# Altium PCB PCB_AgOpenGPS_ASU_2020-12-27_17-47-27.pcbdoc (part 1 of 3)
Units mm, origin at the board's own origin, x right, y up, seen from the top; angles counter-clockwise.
Board outline 200.19 x 135.91 mm, 2 copper layers (Top Layer, Bottom Layer); 260 components, 183 nets, 970 pads, 382 vias.
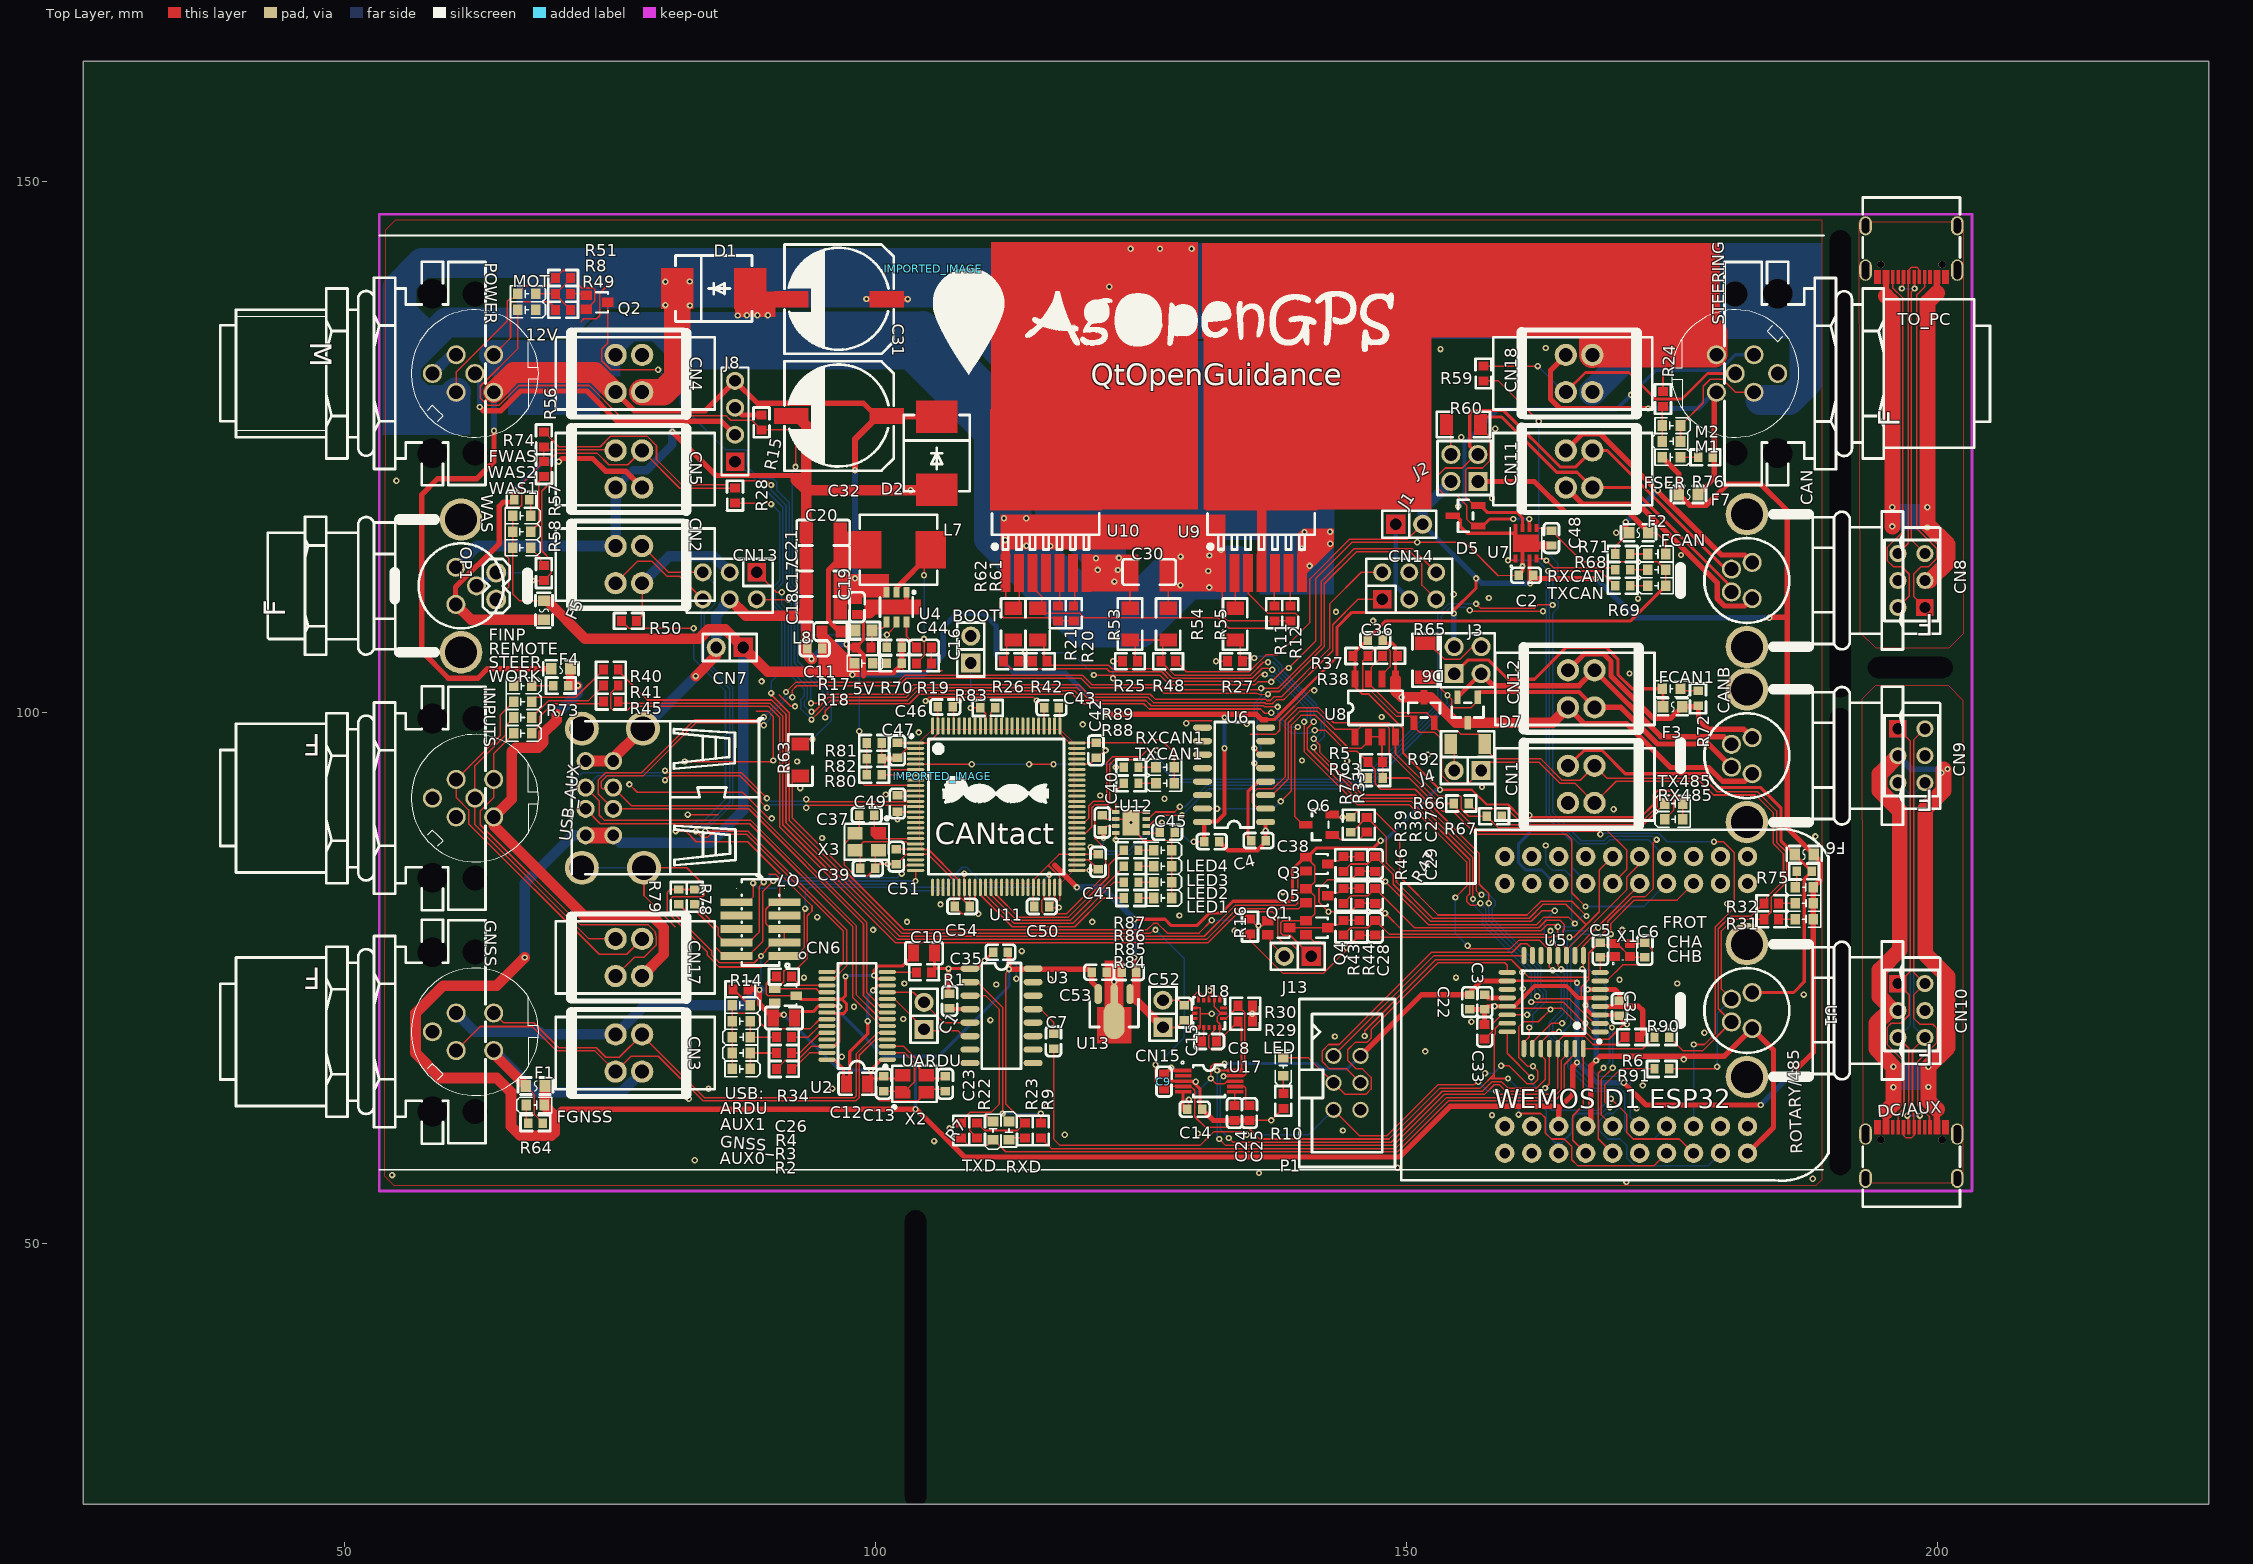
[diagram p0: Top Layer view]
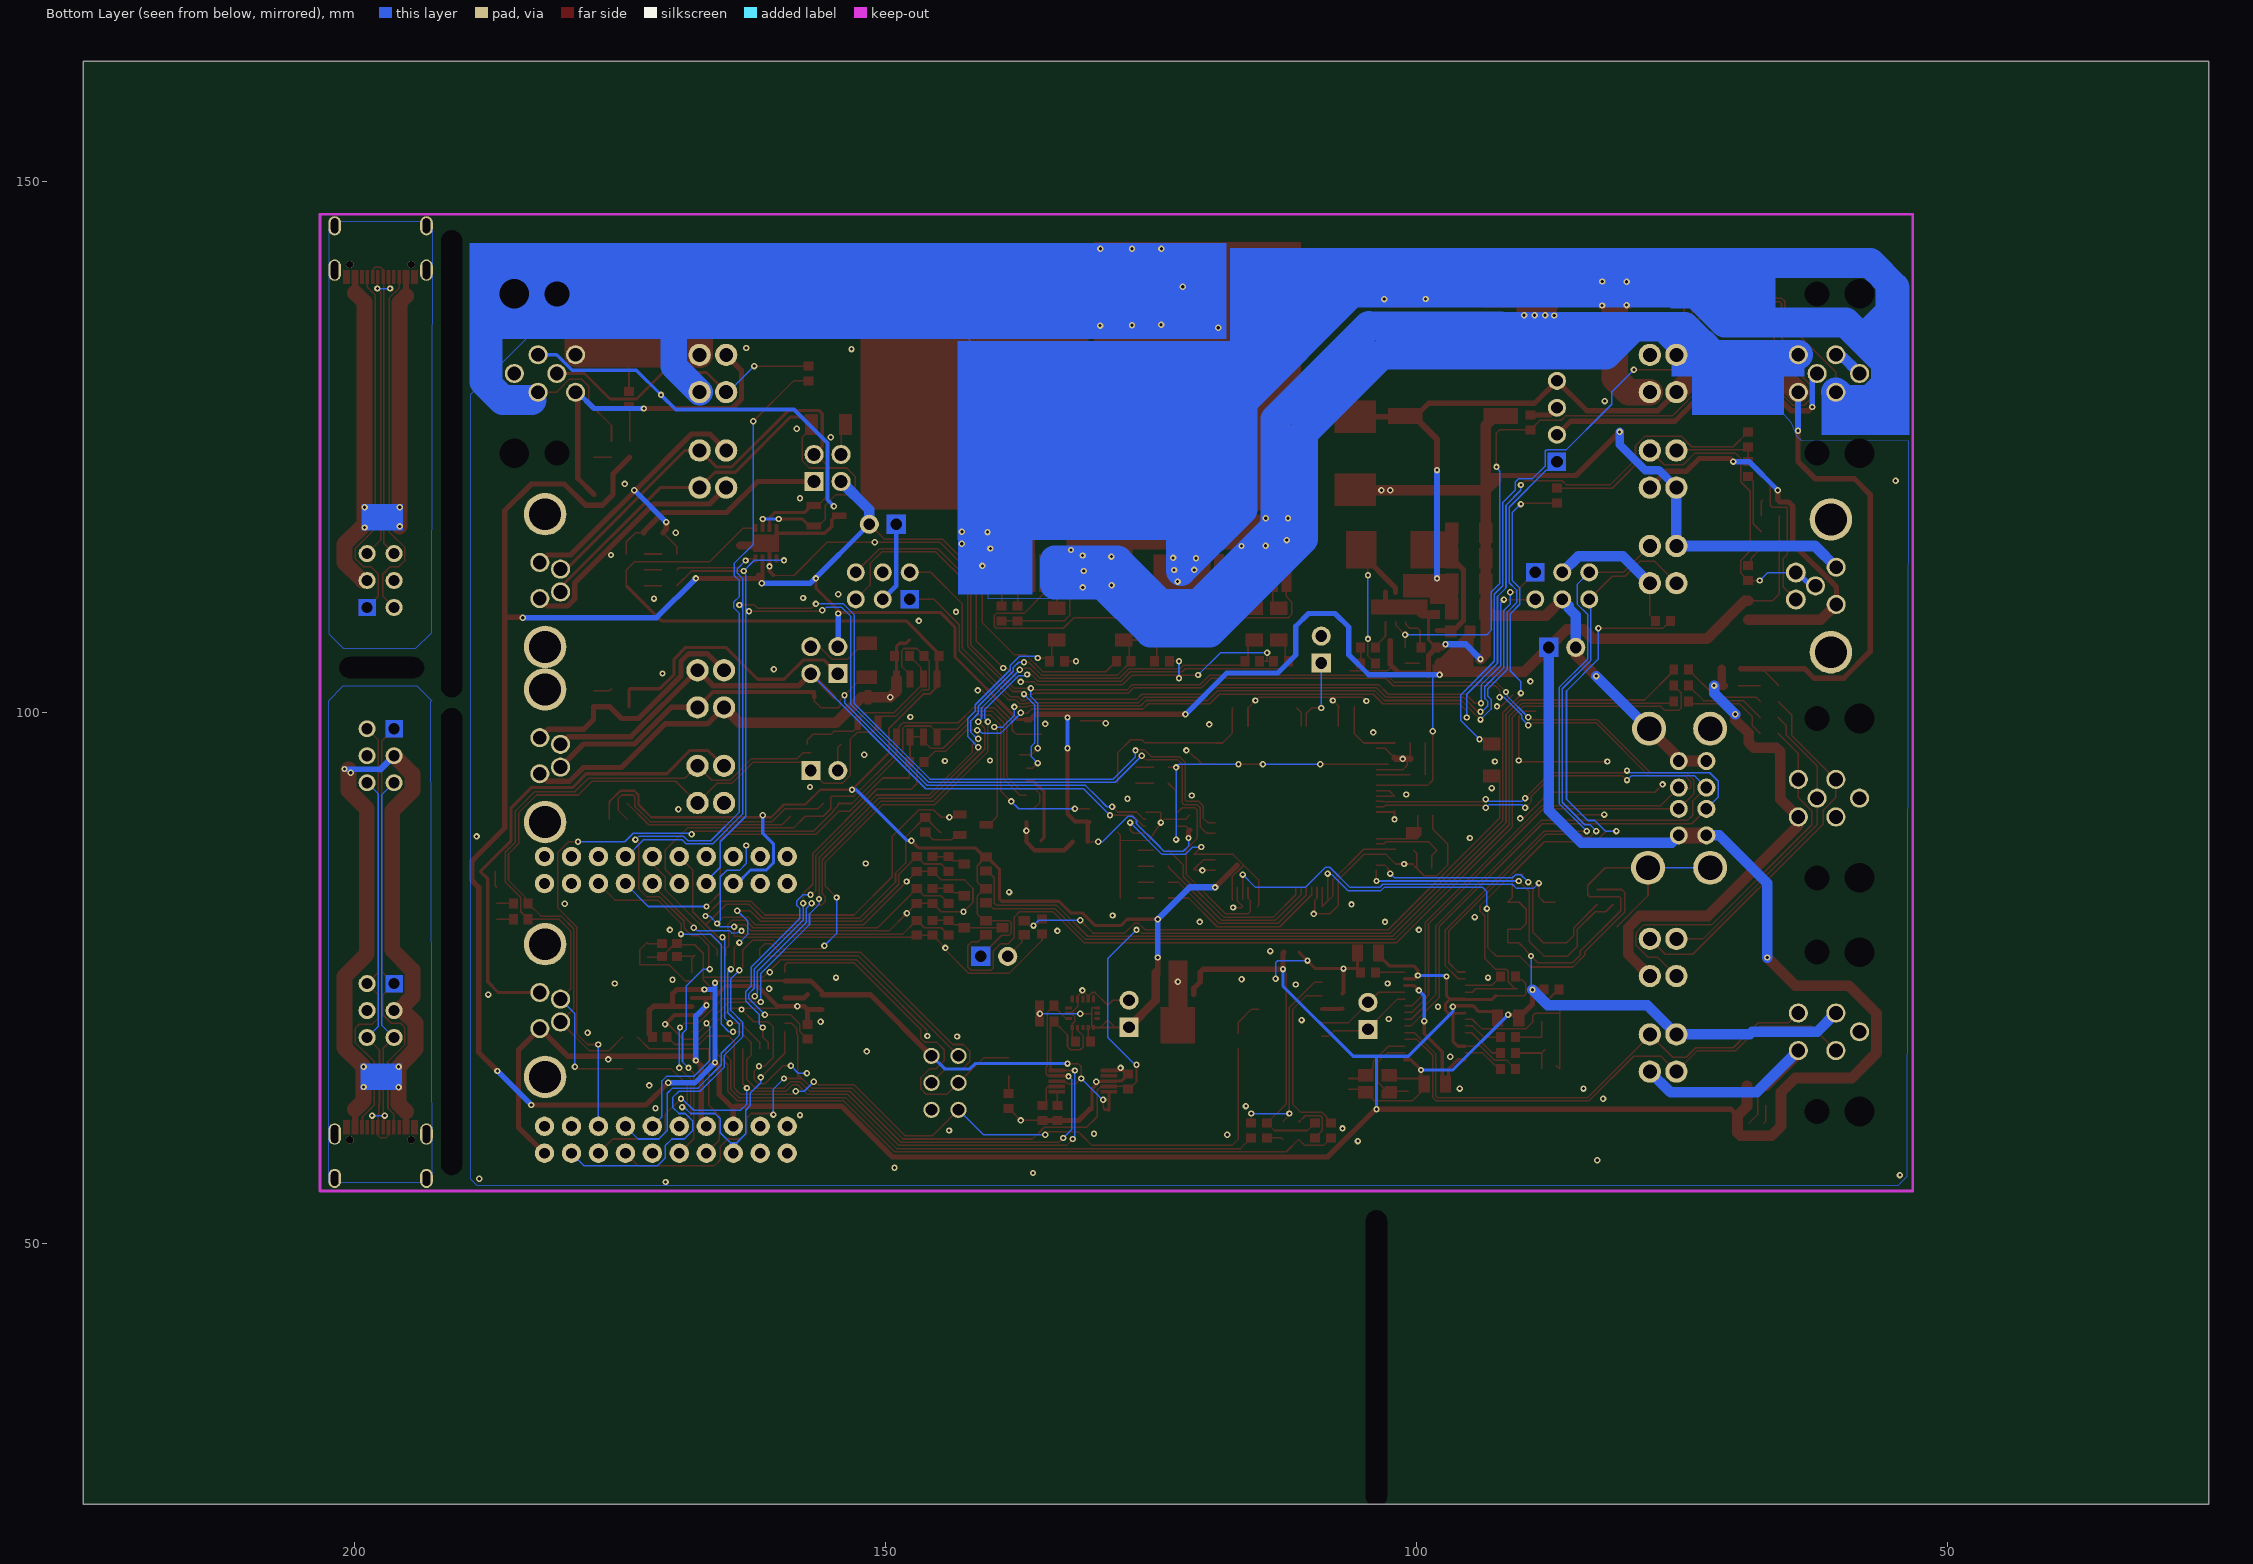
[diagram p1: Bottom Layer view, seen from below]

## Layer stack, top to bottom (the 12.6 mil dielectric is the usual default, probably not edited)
Top Layer: signal copper (thickness not stored)
Dielectric: dielectric 0.32, FR-4, Dk 4.8
Bottom Layer: signal copper (thickness not stored)

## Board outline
225.587,25.4 25.4,25.4 25.4,161.307 225.587,161.307

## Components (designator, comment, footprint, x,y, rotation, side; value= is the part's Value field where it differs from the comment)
5V "FC-D1608WD-460H5" LED0603-RD 98.887,104.6 r180 top
12V "FC-D1608WD-460H5" LED0603-RD 67.187,137.9 r180 top
ARDU "FC-D1608UGK-520D10" LED0603-RD 87.387,70.9 r180 top
AUX0 "FC-D1608UGK-520D10" LED0603-RD 87.387,66.4 r180 top
AUX1 "FC-DA1608BK-470H10" LED0603-RD 87.387,69.4 r0 top
BOOT "A2541WV-2P" HDR-TH_P2.54-H-M_A2541WV-2P#1 108.987,105.9 r90 top
C1 "1uF" C0603#1 106.987,72.8 r270 top
C2 "1uF" C0603#1 161.287,112.9 r180 top
C3 "100nF" C0603#1 157.387,72.7 r270 top
C4 "100nF" C0603#1 131.687,87.8 r0 top
C5 "22pF" C0603#1 168.287,77.6 r270 top
C6 "22pF" C0603#1 172.487,77.6 r90 top
C7 "100nF" C0603#1 116.787,69 r90 top
C8 "100nF" C0603#2 131.437,69 r180 top
C9 "1nF" C0603#2 127.187,65.2 r270 top
C10 "10uF" C0805 104.587,77.3 r180 top
C11 "1uF" C0603#1 94.287,106 r180 top
C12 "10uF" C0805 98.287,65 r180 top
C13 "33pF" C0603#1 100.787,65 r270 top
C14 "1uF" C0603#1 130.087,62.6 r0 top
C15 "1uF" C0603#1 129.087,71.7 r90 top
C16 "100nF" C0603#2 104.587,106.1 r0 top
C17 "10uF" C1206 95.087,112.1 r0 top
C18 "10uF" C1206 95.087,109.7 r0 top
C19 "100nF" C0603#2 98.287,109.9 r90 top
C20 "22uF" C1206 95.087,116.9 r0 top
C21 "22uF" C1206 95.087,114.5 r0 top
C22 "1uF" C0603#1 155.987,72.7 r270 top
C23 "33pF" C0603#1 106.587,65 r270 top
C24 "1nF" C0603#2 133.839,62.251 r90 top
C25 "1nF" C0603#2 135.239,62.251 r90 top
C26 "10uF" C0805 91.387,71.2 r180 top
C27 "100nF" C0603#2 147.087,85.7 r90 top
C28 "100nF" C0603#2 147.087,79.7 r90 top
C29 "100nF" C0603#2 147.087,82.7 r90 top
C30 "10uF" C1206 125.787,113.2 r180 top
C31 "470uF" CAP-SMD_BD10.0-L10.3-W10.3-FD 96.587,138.9 r180 top
C32 "470uF" CAP-SMD_BD10.0-L10.3-W10.3-FD 96.587,127.9 r180 top
C33 "1nF" C0603#2 157.387,69.9 r270 top
C34 "1uF" C0603#1 170.087,72.1 r270 top
C35 "1uF" C0603#1 111.787,77.4 r180 top
C36 "1uF" C0603#1 147.087,106.8 r0 top
C37 "33pF" C0603#1 99.187,90.3 r0 top
C38 "100nF" C0603#1 136.087,87.9 r0 top
C39 "33pF" C0603#1 99.287,85.3 r180 top
C40 "1uF" C0603#1 121.387,89.6 r90 top
C41 "1uF" C0603#1 120.987,85.9 r90 top
C42 "1uF" C0603#1 120.787,96.4 r90 top
C43 "1uF" C0603#1 116.587,100.4 r0 top
C44 "100nF" C0603#1 101.787,106.1 r180 top
C45 "100nF" C0603#1 127.487,88.7 r180 top
C46 "1uF" C0603#1 106.587,100.5 r180 top
C47 "1uF" C0603#1 102.087,96.4 r90 top
C48 "100nF" C0603#1 163.687,116.4 r90 top
C49 "1uF" C0603#3 102.087,91.4 r90 top
C50 "1uF" C0603#1 115.687,81.7 r180 top
C51 "1uF" C0603#1 101.987,86.4 r90 top
C52 "1uF" C0603#1 123.887,75.5 r180 top
C53 "1uF" C0603#1 121.087,75.5 r0 top
C54 "1uF" C0603#1 108.187,81.7 r0 top
CAN "M8 4pole female" "M8 FEMALE 4POLE 90°" 182.087,112.4 r90 top
CANB "M8 4pole female" "M8 FEMALE 4POLE 90°" 182.087,95.9 r90 top
CHA "FC-D1608HYK-588J" LED0603-RD 187.487,82 r0 top
CHB "FC-D1608HOK-600H" LED0603-RD 187.487,80.5 r0 top
CN1 "4x1 push_in connector" "S2C-SMT 3.50/04/180G 3.5SN BK RL" 166.487,93.2 r270 top
CN2 "4x1 push_in connector" "S2C-SMT 3.50/04/180G 3.5SN BK RL" 76.787,113.9 r90 top
CN3 "4x1 push_in connector" "S2C-SMT 3.50/04/180G 3.5SN BK RL" 76.787,67.9 r90 top
CN4 "4x1 push_in connector" "S2C-SMT 3.50/04/180G 3.5SN BK RL" 76.787,131.9 r90 top
CN5 "4x1 push_in connector" "S2C-SMT 3.50/04/180G 3.5SN BK RL" 76.787,122.9 r90 top
CN6 "1315-1206G0M075CP01" HDR-SMD_12P-P1.27-V-M-R2-C6-S7.50 89.187,80.2 r90 top
CN7 "A2541WV-2P" HDR-TH_P2.54-H-M_A2541WV-2P#2 86.287,106.1 r180 top
CN8 "A2541WV-2X3P" HDR-TH_6P-P2.54-V-R2-C3-S2.54_A2541WV-2X3P 197.587,112.4 r90 top
CN9 "A2541WV-2X3P" HDR-TH_6P-P2.54-V-R2-C3-S2.54_A2541WV-2X3P 197.587,95.9 r270 top
CN10 "A2541WV-2X3P" HDR-TH_6P-P2.54-V-R2-C3-S2.54_A2541WV-2X3P 197.587,71.9 r270 top
CN11 "4x1 push_in connector" "S2C-SMT 3.50/04/180G 3.5SN BK RL" 166.287,122.9 r270 top
CN12 "4x1 push_in connector" "S2C-SMT 3.50/04/180G 3.5SN BK RL" 166.487,102.2 r270 top
CN13 "PM254V-12-06-H85" HDR-TH_6P-P2.54-V-F-R2-C3-S2.54 86.287,111.9 r180 top
CN14 "PM254V-12-06-H85" HDR-TH_6P-P2.54-V-F-R2-C3-S2.54 150.287,111.9 r0 top
CN15 "A2541WV-2P" HDR-TH_P2.54-H-M_A2541WV-2P#1 127.087,71.6 r90 top
CN17 "4x1 push_in connector" "S2C-SMT 3.50/04/180G 3.5SN BK RL" 76.787,76.9 r90 top
CN18 "4x1 push_in connector" "S2C-SMT 3.50/04/180G 3.5SN BK RL" 166.287,131.9 r270 top
D1 "SMCJ28A-C140808" SMC_L6.9-W5.9-LS7.9-RD 84.787,139.9 r0 top
D2 "SMCJ28A-C140808" SMC_L6.9-W5.9-LS7.9-RD 105.787,124.4 r270 top
D5 "CDSOT23-T24CAN" SOT-23_L2.9-W1.3-P0.95-LS2.4-BR#1 155.587,118.5 r0 top
D6 "CDSOT23-T24CAN" SOT-23_L2.9-W1.3-P0.95-LS2.4-BR#1 151.687,100.2 r270 top
D7 "CDSOT23-T24CAN" SOT-23_L2.9-W1.3-P0.95-LS2.4-BR#2 155.787,100.2 r90 top
DC/AUX "KH-TYPE-C-16P" USB-C-SMD_KH-TYPE-C-16P#1 197.587,58.5 r0 top
F1 "BSMD0603-050-6V" F0603 67.987,64.8 r0 top
F2 "BSMD0603-050-6V" F0603 171.887,116.9 r180 top
F3 "BSMD0603-050-6V" F0603 175.087,100.5 r0 top
F4 "BSMD0603-050-6V" F0603 70.387,104.1 r0 top
F5 "BSMD0603-050-6V" F0603 68.787,109.6 r270 top
F6 "BSMD0603-050-6V" F0603 187.487,86.6 r180 top
F7 "BSMD0603-050-6V" F0603 176.587,120.5 r0 top
FCAN "FC-DA1608HRK-620D" LED0603-FD 173.587,114.9 r180 top
FCAN1 "FC-DA1608HRK-620D" LED0603-FD 174.988,102.201 r0 top
FGNSS "FC-DA1608HRK-620D" LED0603-FD 67.987,63 r180 top
FINP "FC-DA1608HRK-620D" LED0603-FD 66.787,102.5 r0 top
FROT "FC-DA1608HRK-620D" LED0603-FD 187.487,83.5 r180 top
FSER "FC-DA1608HRK-620D" LED0603-FD 174.987,124 r0 top
FWAS "FC-DA1608HRK-620D" LED0603-FD 66.687,118.5 r0 top
GNSS "M12 4pole female" "M12-D FEMALE 4POLE 90°" 62.287,69.9 r90 top
GNSS_ "FC-DA1608BK-470H10" LED0603-RD 87.387,67.9 r0 top
IMPORTED_IMAGE "IMPORTED_IMAGE" IMPORTED_IMAGE 106.327,93.952 r0 top
IMPORTED_IMAGE "IMPORTED_IMAGE" IMPORTED_IMAGE 105.442,141.785 r0 top
INPUTS "M12A 5pole female" "M12-A FEMALE 4-5POLE 90°" 62.287,91.9 r90 top
J1 "A2541WV-2P" HDR-TH_P2.54-H-M_A2541WV-2P#2 150.287,117.7 r0 top
J2 "A2541WV-2X2P" HDR-TH_4P-P2.54-V-R2-C2-S2.54_A2541WV-2X2P 155.487,123 r90 top
J3 "A2541WV-2X2P" HDR-TH_4P-P2.54-V-R2-C2-S2.54_A2541WV-2X2P 155.787,104.9 r0 top
J4 "A2541WV-2P" HDR-TH_P2.54-H-M_A2541WV-2P#1 155.787,94.5 r180 top
J8 "A2541WV-4P" HDR-TH_4P-P2.54-V 86.787,127.4 r90 top
J13 "A2541WV-2P" HDR-TH_P2.54-H-M_A2541WV-2P#2 139.787,77 r180 top
L7 "5.6uH" IND-SMD_L7.3-W6.6_MHCI06030 102.187,115.3 r180 top
L8 "1500Ω" L0603 95.887,107.6 r180 top
LED "FC-DA1608HRK-620D" LED0603-FD 138.43,66.593 r270 top
LED1 "FC-D1608UGK-520D10" LED0603-RD 127.087,82.5 r180 top
LED2 "FC-DA1608BK-470H10" LED0603-RD 127.087,84 r180 top
LED3 "FC-D1608UGK-520D10" LED0603-RD 127.087,85.5 r180 top
LED4 "FC-DA1608BK-470H10" LED0603-RD 127.087,87 r180 top
M1 "FC-D1608HYK-588J" LED0603-RD 174.987,125.5 r0 top
M2 "FC-D1608HOK-600H" LED0603-RD 174.987,127 r180 top
MOT "FC-D1608WD-460H5" LED0603-RD 67.187,139.4 r180 top
OP1 "Option M8 4pole" 1X02 64.287,113.15 r270 top
P1 "HDR-IDC-2.54-2X3P" IDC-TH_6P-P2.54_C11214 144.429,65.092 r270 top
POWER "M12A 5pole male" "M12-A MALE 4-5POLE 90°" 62.287,131.9 r90 top
Q1 "BC856BW,115" SOT-323-3_L2.2-W1.3-P1.30-LS2.2-BR#1 137.987,79.7 r180 top
Q2 "BC856BW,115" SOT-323-3_L2.2-W1.3-P1.30-LS2.2-BR#1 73.787,138.6 r180 top
Q3 "BC856BW,115" SOT-323-3_L2.2-W1.3-P1.30-LS2.2-BR#1 141.587,85.7 r180 top
Q4 "BC856BW,115" SOT-323-3_L2.2-W1.3-P1.30-LS2.2-BR#1 141.587,79.7 r180 top
Q5 "BC856BW,115" SOT-323-3_L2.2-W1.3-P1.30-LS2.2-BR#1 141.587,82.7 r180 top
Q6 "ZXMS6004FFTA" SOT-23-3_L2.9-W1.6-P1.90-LS2.8-BR 141.787,89.4 r0 top
Q7 "BC856BW,115" SOT-323-3_L2.2-W1.3-P1.30-LS2.2-BR#2 91.537,73.3 r180 top
R1 "2.7k" R0603#1 104.587,75.5 r180 top
R2 "10K" R0603#1 91.387,66.4 r180 top
R3 "1K" R0603#1 91.387,67.9 r180 top
R4 "1K" R0603#1 91.387,69.4 r0 top
R5 "1K" R0603#1 147.087,95.3 r180 top
R6 "1K" R0603#1 171.287,69.4 r0 top
R7 "1K" R0603#1 108.087,60.6 r270 top
R8 "10K" R0603#1 70.587,139.4 r0 top
R9 "1K" R0603#1 115.587,60.6 r90 top
R10 "1K" R0603#1 138.429,63.392 r90 top
R11 "1K" R0603#1 137.587,109.3 r90 top
R12 "1K" R0603#1 139.087,109.3 r90 top
R14 "1K" R0603#1 87.287,73.9 r180 top
R15 "10K" R0603#1 89.287,127.3 r90 top
R16 "10K" R0603#1 135.287,79.8 r270 top
R17 "51K" R0603#2 98.887,107.7 r180 top
R18 "10K" R0603#1 98.887,106.1 r0 top
R19 "10" R0603#1 104.587,104.6 r0 top
R20 "1K" R0603#1 118.687,109.3 r270 top
R21 "1K" R0603#1 117.187,109.3 r270 top
R22 "1K" R0603#1 109.587,60.6 r90 top
R23 "1K" R0603#1 114.087,60.6 r90 top
R24 "2.7k" R0603#1 174.187,129.5 r90 top
R25 "2k2" R0603#1 123.987,104.8 r180 top
R26 "2k2" R0603#1 112.787,104.8 r0 top
R27 "2k2" R0603#1 133.887,104.8 r180 top
R28 "10K" R0603#1 86.787,120.4 r270 top
R29 "1K" R0603#1 134.839,70.851 r0 top
R30 "1K" R0603#1 134.839,72.351 r0 top
R31 "1K" R0603#1 184.387,80.5 r0 top
R32 "1K" R0603#1 184.387,82 r0 top
R33 "10K" R0603#1 146.287,89.4 r90 top
R34 "10K" R0603#1 91.387,75.1 r180 top
R36 "680R" R0603#1 145.587,85.7 r90 top
R37 "1K" R0603#1 145.687,105.3 r180 top
R38 "1K" R0603#1 148.487,105.3 r0 top
R39 "10K" R0603#1 144.087,85.7 r90 top
R40 "1K" R0603#1 75.087,104 r180 top
R41 "1K" R0603#1 75.087,102.5 r180 top
R42 "2k2" R0603#1 115.487,104.8 r180 top
R43 "10K" R0603#1 144.087,79.7 r90 top
R44 "680R" R0603#1 145.587,79.7 r90 top
R45 "1K" R0603#1 75.087,101 r180 top
R46 "10K" R0603#1 144.087,82.7 r90 top
R47 "680R" R0603#1 145.587,82.7 r90 top
R48 "10K" R0603#1 127.587,104.8 r180 top
R49 "10K" R0603#1 70.587,137.9 r0 top
R50 "10K" R0603#1 76.787,108.6 r180 top
R51 "10K" R0603#1 70.587,140.9 r180 top
R53 "8.2K" RES-SMD_L3.5-W1.5 123.987,108.3 r90 top
R54 "8.2K" RES-SMD_L3.5-W1.5 127.587,108.3 r90 top
R55 "8.2K" RES-SMD_L3.5-W1.5 133.887,108.3 r90 top
R56 "10K" R0603#1 68.787,125.7 r90 top
R57 "1K" R0603#1 68.787,122.9 r270 top
R58 "1K" R0603#1 68.787,113.1 r90 top
R59 "1K" R0603#1 157.287,131.9 r90 top
R60 "120" R1206#1 155.387,127.1 r180 top
R61 "8.2K" RES-SMD_L3.5-W1.5 115.287,108.3 r90 top
R62 "8.2K" RES-SMD_L3.5-W1.5 112.987,108.3 r270 top
R63 "8.2K" RES-SMD_L3.5-W1.5 92.937,95.5 r270 top
R64 "1K" R0603#3 67.987,61.3 r0 top
R65 "120" R1206#1 151.787,104.9 r90 top
R66 "1K" R0603#3 155.187,91.4 r180 top
R67 "1K" R0603#3 158.287,90.2 r180 top
R68 "1K" R0603#3 170.387,113.4 r180 top
R69 "1K" R0603#3 170.387,111.9 r180 top
R70 "10K" R0603#3 101.787,104.6 r180 top
R71 "2.7k" R0603#3 170.387,114.9 r180 top
R72 "2.7k" R0603#3 177.487,101.3 r270 top
R73 "10K" R0603#3 70.387,102.5 r0 top
R74 "10K" R0603#3 66.687,120 r180 top
R75 "1K" R0603#3 187.487,85 r0 top
R76 "1K" R0603#3 178.187,124 r180 top
R77 "10K" R0603#3 144.787,89.4 r90 top
R78 "10K" R0603#3 82.987,82.6 r270 top
R79 "10K" R0603#3 81.487,82.6 r270 top
R80 "10K" R0603#3 99.887,94.1 r180 top
R81 "2.7k" R0603#3 99.887,97.1 r0 top
R82 "10K" R0603#3 99.887,95.6 r0 top
R83 "10" R0603#3 110.587,100.4 r0 top
R84 "1K" R0603#3 124.087,82.5 r180 top
R85 "1K" R0603#3 124.087,84 r180 top
R86 "1K" R0603#3 124.087,85.5 r180 top
R87 "1K" R0603#3 124.087,87 r180 top
R88 "1K" R0603#3 124.087,93.3 r180 top
R89 "1K" R0603#3 124.087,94.8 r180 top
R90 "1K" R0603#3 174.087,69.4 r180 top
R91 "1K" R0603#3 174.087,66.4 r180 top
R92 "120" R1206#2 155.787,97 r0 top
R93 "10K" R0603#3 147.087,93.8 r180 top
REMOTE "FC-D1608HYK-588J" LED0603-RD 66.787,101 r180 top
ROTARY/485 "M8 4pole female" "M8 FEMALE 4POLE 90°" 182.087,71.9 r90 top
RX485 "FC-D1608UGK-520D10" LED0603-RD 175.187,89.9 r0 top
RXCAN "FC-D1608UGK-520D10" LED0603-RD 173.587,113.4 r0 top
RXCAN1 "FC-D1608UGK-520D10" LED0603-RD 127.287,94.8 r0 top
RXD "FC-D1608UGK-520D10" LED0603-RD 112.587,60.6 r270 top
STEER "FC-D1608HYK-588J" LED0603-RD 66.787,99.5 r180 top
STEERING "M12A 5pole female" "M12-A FEMALE 4-5POLE 90°" 180.987,131.9 r270 top
TO_PC "KH-TYPE-C-16P" USB-C-SMD_KH-TYPE-C-16P#2 197.587,143.4 r180 top
TX485 "FC-DA1608BK-470H10" LED0603-RD 175.187,91.4 r0 top
TXCAN "FC-DA1608BK-470H10" LED0603-RD 173.587,111.9 r0 top
TXCAN1 "FC-DA1608BK-470H10" LED0603-RD 127.287,93.3 r0 top
TXD "FC-DA1608BK-470H10" LED0603-RD 111.087,60.6 r90 top
U1 "TG_WEMOS_D1_ESP32(CLONE)" "WEMOS-D1 ESP32" 184.687,86.4 r270 top
U2 "FE1.1S" SSOP-28_L9.9-W3.9-P0.64-LS6.0-BL 98.287,71.4 r90 top
U3 "CH340B" SOIC-16_L9.9-W3.9-P1.27-LS6.0-BL 111.887,71.4 r270 top
U4 "TPS56339" SOT-23-6_L2.9-W1.6-P0.95-LS2.8-BL 101.987,109.9 r180 top
U5 "ATMEGA328P-AU" TQFP-32_L7.0-W7.0-P0.80-LS9.0-BL 163.887,72.7 r90 top
U6 "CH340B" SOIC-16_L9.9-W3.9-P1.27-LS6.0-BL 133.787,94.1 r90 top
U7 "TJA1051TK/3,118" HVSON-8_L3.0-W3.0-P0.65-BL-EP#1 161.287,115.9 r0 top
U8 "KY3485LEEN" SO-8_L4.9-W3.9-P1.27-LS5.9-BL 147.087,100.4 r0 top
U9 "BTN8982TAAUMA1" TO-263-7_L10.2-W10.4-P1.27-LS14.4-B 136.387,118.45 r270 top
U10 "BTN8982TAAUMA1" TO-263-7_L10.2-W10.4-P1.27-LS14.4-B 116.087,118.45 r270 top
U11 "LPC54616J512BD100" TQFP-100_14X14X05P 105.387,98.7 r0 top
U12 "TJA1051TK/3,118" HVSON-8_L3.0-W3.0-P0.65-BL-EP#2 124.087,89.6 r270 top
U13 "UR133AG-33-AB3-B-R" SOT-89_L4.5-W2.5-P1.50-LS4.2-BR 122.487,72.2 r90 top
U17 "ADS1115IDGSR" MSOP-10_L3.0-W3.0-P0.50-LS5.0-BL 131.439,65.251 r270 top
U18 "MMA8452QR1_C11360" QFN-16_L3.0-W3.0-P0.50-TL_MMA8452QR1 131.439,71.651 r90 top
UARDU "A2541WV-2P" HDR-TH_P2.54-H-M_A2541WV-2P#1 104.588,71.401 r90 top
USB: "FC-D1608UGK-520D10" LED0603-RD 87.387,72.4 r180 top
USB_AUX "Double layer DIP 90° white" USB-A-TH_USB-M-51 75.286,91.9 r90 top
WAS "M8 3pole female" "M8 FEMALE 3POLE 90°" 60.987,111.9 r270 top
WAS1 "FC-D1608HYK-588J" LED0603-RD 66.687,115.5 r180 top
WAS2 "FC-D1608HOK-600H" LED0603-RD 66.687,117 r180 top
WORK "FC-D1608HYK-588J" LED0603-RD 66.787,98 r180 top
X1 "16MHz" OSC-SMD_4P-L2.0-W1.6-BL 170.387,77.6 r0 top
X2 "12MHz" OSC-SMD_4P-L3.2-W2.5-BL#1 103.687,65 r0 top
X3 "12MHz" OSC-SMD_4P-L3.2-W2.5-BL#2 99.187,87.8 r180 top

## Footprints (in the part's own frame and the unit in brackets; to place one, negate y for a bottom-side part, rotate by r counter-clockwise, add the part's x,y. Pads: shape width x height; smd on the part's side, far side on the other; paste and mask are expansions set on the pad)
1X02 [mil]
  round 74 hole 51.18: 1(0,0) 2(100,0)
  silkscreen extent -50,-50 150,50
C0603#1 [mm]
  rect 0.8x0.9 smd: 1(-0.7,0) 2(0.7,0)
  silkscreen extent -1.4,-0.7 1.4,0.72
C0603#2 [mm]
  round 0 smd: 1(-0.7,0) 2(0.7,0)
  Top Layer region: -1.1,0.45 -0.3,0.45 -0.3,-0.45 -1.1,-0.45
  Top Layer region: 0.3,0.45 1.1,0.45 1.1,-0.45 0.3,-0.45
  silkscreen extent -1.4,-0.7 1.4,0.72
C0603#3 [mm]
  rect 0.8x0.9 smd: 1(-0.775,0) 2(0.775,0)
  silkscreen extent -1.4,-0.7 1.4,0.72
C0805 [mm]
  round 0 smd: 1(-1,0) 2(1,0)
  Top Layer region: -1.5,0.775 -0.5,0.775 -0.5,-0.775 -1.5,-0.775
  Top Layer region: 0.5,0.775 1.5,0.775 1.5,-0.775 0.5,-0.775
  silkscreen extent -1.75,-1.04 1.75,1.04
C1206 [mm]
  round 0 smd: 1(-1.6,0) 2(1.6,0)
  Top Layer region: -2.2,0.95 -1,0.95 -1,-0.95 -2.2,-0.95
  Top Layer region: 1,0.95 2.2,0.95 2.2,-0.95 1,-0.95
  silkscreen extent -2.5,-1.2 2.5,1.2
CAP-SMD_BD10.0-L10.3-W10.3-FD [mm]
  round 0 smd: 1(-4.5,0) 2(4.5,0)
  Top Layer region: -2.9,-0.75 -6.1,-0.75 -6.1,0.75 -2.9,0.75
  Top Layer region: 6.1,-0.75 2.9,-0.75 2.9,0.75 6.1,0.75
  silkscreen extent -5.15,-5.15 5.15,5.15
F0603 [mm]
  rect 1x1.1 smd: 1(-0.9,0) 2(0.9,0)
  silkscreen extent -1.65,-0.8 1.65,0.8
HDR-SMD_12P-P1.27-V-M-R2-C6-S7.50 [mm]
  rect 0.74x3 smd: 1(-3.175,-2.25) 2(-3.175,2.25) 3(-1.905,-2.25) 4(-1.905,2.25) 5(-0.635,-2.25) 6(-0.635,2.25) 7(0.635,-2.25) 8(0.635,2.25) 9(1.905,-2.25) 10(1.905,2.25)
  rect 0.1x0.1 smd: 11(3.175,-2.25) 12(3.175,2.25)
  silkscreen extent -4.24,-2.72 4.06,1.78
HDR-TH_4P-P2.54-V [mm]
  round 0 hole 1.1: 1(-3.81,0)
  round 1.7 hole 1.1: 2(-1.27,0) 3(1.27,0) 4(3.81,0)
  Top Layer region: -4.66,0.85 -2.96,0.85 -2.96,-0.85 -4.66,-0.85
  Bottom Layer region: -4.66,0.85 -2.96,0.85 -2.96,-0.85 -4.66,-0.85
  silkscreen extent -5.08,-1.27 5.08,1.27
HDR-TH_4P-P2.54-V-R2-C2-S2.54_A2541WV-2X2P [mm]
  rect 1.8x1.8 hole 1.2: 1(-1.27,-1.27)
  round 1.8 hole 1.2: 2(-1.27,1.27) 3(1.27,-1.27) 4(1.27,1.27)
  silkscreen extent -2.54,-2.54 2.54,2.54
HDR-TH_6P-P2.54-V-F-R2-C3-S2.54 [mm]
  round 0 hole 1.1: 1(-2.54,-1.27)
  round 1.7 hole 1.1: 2(-2.54,1.27) 3(0,-1.27) 4(0,1.27) 5(2.54,-1.27) 6(2.54,1.27)
  Top Layer region: -3.39,-0.42 -1.69,-0.42 -1.69,-2.12 -3.39,-2.12
  Bottom Layer region: -3.39,-0.42 -1.69,-0.42 -1.69,-2.12 -3.39,-2.12
  silkscreen extent -4.04,-2.54 4.04,2.54
HDR-TH_6P-P2.54-V-R2-C3-S2.54_A2541WV-2X3P [mm]
  round 0 hole 1.05: 1(-2.54,-1.27)
  round 1.6 hole 1.05: 2(-2.54,1.27) 3(0,-1.27) 4(0,1.27) 5(2.54,-1.27) 6(2.54,1.27)
  Top Layer region: -3.34,-0.47 -1.74,-0.47 -1.74,-2.07 -3.34,-2.07
  Bottom Layer region: -3.34,-0.47 -1.74,-0.47 -1.74,-2.07 -3.34,-2.07
  silkscreen extent -3.81,-2.54 3.81,2.54
HDR-TH_P2.54-H-M_A2541WV-2P#1 [mm]
  rect 1.8x1.8 hole 1.1: 1(-1.27,0)
  round 1.8 hole 1.1: 2(1.27,0)
  silkscreen extent -2.54,-1.27 2.54,1.27
HDR-TH_P2.54-H-M_A2541WV-2P#2 [mm]
  round 0 hole 1.1: 1(-1.27,0)
  round 1.8 hole 1.1: 2(1.27,0)
  Top Layer region: -2.17,0.9 -0.37,0.9 -0.37,-0.9 -2.17,-0.9
  Bottom Layer region: -2.17,0.9 -0.37,0.9 -0.37,-0.9 -2.17,-0.9
  silkscreen extent -2.54,-1.27 2.54,1.27
HVSON-8_L3.0-W3.0-P0.65-BL-EP#1 [mil]
  round 0 smd: 1(-39,-56.4) 2(-13,-56.4) 3(13,-56.4) 4(39,-56.4) 5(39,56.4) 6(13,56.4) 7(-13,56.4) 8(-39,56.4) 9(0,0)
  Top Layer region: -46,-42.4 -32,-42.4 -32,-70.4 -46,-70.4
  Top Layer region: -20,-42.4 -6,-42.4 -6,-70.4 -20,-70.4
  Top Layer region: 6,-42.4 20,-42.4 20,-70.4 6,-70.4
  Top Layer region: 32,-42.4 46,-42.4 46,-70.4 32,-70.4
  Top Layer region: 32,70.4 46,70.4 46,42.4 32,42.4
  Top Layer region: 6,70.4 20,70.4 20,42.4 6,42.4
  Top Layer region: -20,70.4 -6,70.4 -6,42.4 -20,42.4
  Top Layer region: -46,70.4 -32,70.4 -32,42.4 -46,42.4
  Top Layer region: -47.24,31.5 47.24,31.5 47.24,-31.5 -47.24,-31.5
  silkscreen extent -59,-89 59,59
HVSON-8_L3.0-W3.0-P0.65-BL-EP#2 [mil]
  rect 14x28 smd: 1(-39,-56.4) 2(-13,-56.4) 3(13,-56.4) 4(39,-56.4) 5(39,56.4) 6(13,56.4) 7(-13,56.4) 8(-39,56.4)
  rect 94.49x62.99 smd: 9(0,0)
  silkscreen extent -59,-89 59,59
IDC-TH_6P-P2.54_C11214 [mil]
  round 60 hole 43.3: 1(-100,-50) 2(-100,50) 3(0,-50) 4(0,50) 5(100,-50) 6(100,50)
  silkscreen extent -311,-177 312,178
IMPORTED_IMAGE [mm]
  silkscreen extent 0,-2.57 10,0
IND-SMD_L7.3-W6.6_MHCI06030 [mm]
  round 0 smd: 1(-3.025,0) 2(3.025,0)
  Top Layer region: -4.425,1.75 -1.625,1.75 -1.625,-1.75 -4.425,-1.75
  Top Layer region: 1.625,1.75 4.425,1.75 4.425,-1.75 1.625,-1.75
  silkscreen extent -3.65,-3.3 3.65,3.3
L0603 [mm]
  round 0 smd: 1(-0.9,0) 2(0.9,0)
  Top Layer region: 0.4,0.55 1.4,0.55 1.4,-0.55 0.4,-0.55
  Top Layer region: -1.4,0.55 -0.4,0.55 -0.4,-0.55 -1.4,-0.55
  silkscreen extent -1.68,-0.85 1.68,0.85
LED0603-FD [mm]
  rect 0.9x1 smd: 1(-0.85,0) 2(0.85,0)
  silkscreen extent -1.55,-0.75 1.75,0.75
LED0603-RD [mm]
  rect 0.9x1 smd: 1(-0.85,0) 2(0.85,0)
  silkscreen extent -1.75,-0.75 1.55,0.75
"M8 FEMALE 3POLE 90°" [mm]
  round 1.8 hole 1.3: 1(1.75,-0.5) 3(-1.75,-0.5) 4(0,1.45)
  round 4 hole 3: Shield(-6.25,0) Shield(6.25,0)
  silkscreen extent -6.5,-18.2 6.5,6.25
"M8 FEMALE 4POLE 90°" [mm]
  round 1.8 hole 1.3: 1(1.7,-0.5) 2(1.075,1.45) 3(-1.7,-0.5) 4(-1.075,1.45)
  round 4 hole 3: Shield(-6.25,0) Shield(6.25,0)
  silkscreen extent -6.5,-18.2 6.5,6.25
"M12-A FEMALE 4-5POLE 90°" [mm]
  round 1.8 hole 1.3: 1(1.768,-1.768) 2(-1.768,-1.768) 3(-1.768,1.768) 4(1.768,1.768) 5(0,0) Shield(0,4)
  round 1 hole 2.35 unplated: ""(-7.5,0) ""(7.5,0)
  round 2.35 hole 2.8 unplated: ""(-7.5,4) ""(7.5,4)
  silkscreen extent -10.54,-6 10.54,24
"M12-A MALE 4-5POLE 90°" [mm]
  round 1.8 hole 1.3: 1(-1.768,-1.768) 2(1.768,-1.768) 3(1.768,1.768) 4(-1.768,1.768) 5(0,0) Shield(0,4)
  round 1 hole 2.35 unplated: ""(-7.5,0) ""(7.5,0)
  round 2.35 hole 2.8 unplated: ""(-7.5,4) ""(7.5,4)
  silkscreen extent -10.54,-6 10.54,24
"M12-D FEMALE 4POLE 90°" [mm]
  round 1.8 hole 1.3: 1(1.768,-1.768) 2(-1.768,-1.768) 3(-1.768,1.768) 4(1.768,1.768) Shield(0,4)
  round 1 hole 2.35 unplated: ""(-7.5,0) ""(7.5,0)
  round 2.35 hole 2.8 unplated: ""(-7.5,4) ""(7.5,4)
  silkscreen extent -10.54,-6 10.54,24
MSOP-10_L3.0-W3.0-P0.50-LS5.0-BL [mil]
  round 0 smd: 1(-39.37,-96.5) 2(-19.68,-96.5) 3(0,-96.5) 4(19.69,-96.5) 5(39.37,-96.5) 6(39.37,96.5) 7(19.69,96.5) 8(0,96.5) 9(-19.68,96.5) 10(-39.37,96.5)
  Top Layer region: -45.37,-126.03 -45.37,-66.97 -33.37,-66.97 -33.37,-126.03
  Top Layer region: -25.68,-126.03 -25.68,-66.97 -13.68,-66.97 -13.68,-126.03
  Top Layer region: -6,-126.03 -6,-66.97 6,-66.97 6,-126.03
  Top Layer region: 13.69,-126.03 13.69,-66.97 25.69,-66.97 25.69,-126.03
  Top Layer region: 33.37,-126.03 33.37,-66.97 45.37,-66.97 45.37,-126.03
  Top Layer region: 33.37,66.97 33.37,126.03 45.37,126.03 45.37,66.97
  Top Layer region: 13.69,66.97 13.69,126.03 25.69,126.03 25.69,66.97
  Top Layer region: -6,66.97 -6,126.03 6,126.03 6,66.97
  Top Layer region: -25.68,66.97 -25.68,126.03 -13.68,126.03 -13.68,66.97
  Top Layer region: -45.37,66.97 -45.37,126.03 -33.37,126.03 -33.37,66.97
  silkscreen extent -74,-103 59,59
OSC-SMD_4P-L2.0-W1.6-BL [mm]
  round 0 smd: 1(-0.7,-0.6) 2(0.7,-0.6) 3(0.7,0.6) 4(-0.7,0.6)
  Top Layer region: -1.15,1 -0.25,1 -0.25,0.2 -1.15,0.2
  Top Layer region: 0.25,1 1.15,1 1.15,0.2 0.25,0.2
  Top Layer region: 0.25,-0.2 1.15,-0.2 1.15,-1 0.25,-1
  Top Layer region: -1.15,-0.2 -0.25,-0.2 -0.25,-1 -1.15,-1
  silkscreen extent -1.3,-1.37 1.3,0.9
OSC-SMD_4P-L3.2-W2.5-BL#1 [mil]
  round 0 smd: 1(-43.31,-31.5) 2(43.31,-31.5) 3(43.31,31.5) 4(-43.31,31.5)
  Top Layer region: 15.75,54.14 70.86,54.14 70.86,8.86 15.75,8.86
  Top Layer region: -70.87,-8.86 -30,-8.86 -15.75,-23.78 -15.75,-54.14 -70.87,-54.14
  Top Layer region: -70.87,54.14 -15.75,54.14 -15.75,8.86 -70.87,8.86
  Top Layer region: 15.75,-8.86 70.86,-8.86 70.86,-54.14 15.75,-54.14
  silkscreen extent -83,-93 83,67
OSC-SMD_4P-L3.2-W2.5-BL#2 [mil]
  round 0 smd: 1(-43.31,-31.5)
  rect 55.12x45.28 smd: 2(43.31,-31.5) 3(43.31,31.5) 4(-43.31,31.5)
  Top Layer region: -70.87,-8.86 -30,-8.86 -15.75,-23.78 -15.76,-54.14 -70.87,-54.14
  silkscreen extent -83,-93 83,67
QFN-16_L3.0-W3.0-P0.50-TL_MMA8452QR1 [mm]
  round 0 smd: 1(-1.35,1) 2(-1.35,0.5) 3(-1.35,0) 4(-1.35,-0.5) 5(-1.35,-1) 6(-0.5,-1.35) 7(0,-1.35) 8(0.5,-1.35) 9(1.35,-1) 10(1.35,-0.5) 11(1.35,0) 12(1.35,0.5) 13(1.35,1) 14(0.5,1.35) 15(0,1.35) 16(-0.5,1.35)
  Top Layer region: -1.575,1.125 -1.125,1.125 -1.125,0.875 -1.575,0.875
  Top Layer region: -1.575,0.625 -1.125,0.625 -1.125,0.375 -1.575,0.375
  Top Layer region: -1.575,0.125 -1.125,0.125 -1.125,-0.125 -1.575,-0.125
  Top Layer region: -1.575,-0.375 -1.125,-0.375 -1.125,-0.625 -1.575,-0.625
  Top Layer region: -1.575,-0.875 -1.125,-0.875 -1.125,-1.125 -1.575,-1.125
  Top Layer region: -0.625,-1.65 -0.625,-1.05 -0.375,-1.05 -0.375,-1.65
  Top Layer region: -0.125,-1.65 -0.125,-1.05 0.125,-1.05 0.125,-1.65
  Top Layer region: 0.375,-1.65 0.375,-1.05 0.625,-1.05 0.625,-1.65
  Top Layer region: 1.65,-1.125 1.05,-1.125 1.05,-0.875 1.65,-0.875
  Top Layer region: 1.65,-0.625 1.05,-0.625 1.05,-0.375 1.65,-0.375
  Top Layer region: 1.65,-0.125 1.05,-0.125 1.05,0.125 1.65,0.125
  Top Layer region: 1.65,0.375 1.05,0.375 1.05,0.625 1.65,0.625
  Top Layer region: 1.65,0.875 1.05,0.875 1.05,1.125 1.65,1.125
  Top Layer region: 0.625,1.575 0.625,1.125 0.375,1.125 0.375,1.575
  Top Layer region: 0.125,1.575 0.125,1.125 -0.125,1.125 -0.125,1.575
  Top Layer region: -0.375,1.575 -0.375,1.125 -0.625,1.125 -0.625,1.575
  silkscreen extent -1.98,-1.5 1.5,1.5
R0603#1 [mm]
  round 0 smd: 1(-0.7,0) 2(0.7,0)
  Top Layer region: 0.3,0.45 1.1,0.45 1.1,-0.45 0.3,-0.45
  Top Layer region: -1.1,0.45 -0.3,0.45 -0.3,-0.45 -1.1,-0.45
  silkscreen extent -1.4,-0.75 1.4,0.76
R0603#2 [mm]
  rect 1x1.1 smd: 1(-0.8,0) 2(0.8,0)
  silkscreen extent -1.55,-0.8 1.55,0.81
R0603#3 [mm]
  rect 0.8x0.9 smd: 1(-0.7,0) 2(0.7,0)
  silkscreen extent -1.4,-0.75 1.4,0.76
R1206#1 [mm]
  round 0 smd: 1(-1.6,0) 2(1.6,0)
  Top Layer region: 1,0.95 2.2,0.95 2.2,-0.95 1,-0.95
  Top Layer region: -2.2,0.95 -1,0.95 -1,-0.95 -2.2,-0.95
  silkscreen extent -2.5,-1.2 2.5,1.2
R1206#2 [mm]
  rect 1.2x1.9 smd: 1(-1.6,0) 2(1.6,0)
  silkscreen extent -2.5,-1.2 2.5,1.2
RES-SMD_L3.5-W1.5 [mm]
  round 0 smd: 1(-1.5,0) 2(1.5,0)
  Top Layer region: -2.1,0.8 -0.9,0.8 -0.9,-0.8 -2.1,-0.8
  Top Layer region: 0.9,0.8 2.1,0.8 2.1,-0.8 0.9,-0.8
  silkscreen extent -2.41,-1.14 2.41,1.14
"S2C-SMT 3.50/04/180G 3.5SN BK RL" [mm]
  round 2.1 hole 1.3: 1(-1.75,-1.25) 2(-1.75,1.25) 3(1.75,-1.25) 4(1.75,1.25)
  silkscreen extent -4.1,-8.1 4.1,6.9
SMC_L6.9-W5.9-LS7.9-RD [mm]
  round 0 smd: 1(-3.435,0) 2(3.435,0)
  Top Layer region: 4.95,-1.91 1.92,-1.91 1.92,1.91 4.95,1.91
  Top Layer region: -1.92,-1.91 -4.95,-1.91 -4.95,1.91 -1.92,1.91
  silkscreen extent -3.6,-3.11 3.6,3.11
SO-8_L4.9-W3.9-P1.27-LS5.9-BL [mm]
  round 0 smd: 1(-1.905,-2.72) 2(-0.635,-2.72) 3(0.635,-2.72) 4(1.905,-2.72) 5(1.905,2.72) 6(0.635,2.72) 7(-0.635,2.72) 8(-1.905,2.72)
  Top Layer region: -2.23,-1.945 -1.58,-1.945 -1.58,-3.495 -2.23,-3.495
  Top Layer region: -0.96,-1.945 -0.31,-1.945 -0.31,-3.495 -0.96,-3.495
  Top Layer region: 0.31,-1.945 0.96,-1.945 0.96,-3.495 0.31,-3.495
  Top Layer region: 1.58,-1.945 2.23,-1.945 2.23,-3.495 1.58,-3.495
  Top Layer region: 1.58,3.495 2.23,3.495 2.23,1.945 1.58,1.945
  Top Layer region: 0.31,3.495 0.96,3.495 0.96,1.945 0.31,1.945
  Top Layer region: -0.96,3.495 -0.31,3.495 -0.31,1.945 -0.96,1.945
  Top Layer region: -2.23,3.495 -1.58,3.495 -1.58,1.945 -2.23,1.945
  silkscreen extent -2.54,-1.61 2.6,1.63
SOIC-16_L9.9-W3.9-P1.27-LS6.0-BL [mm]
  oval 0.6x1.798 smd: 1(-4.445,-2.972) 2(-3.175,-2.972) 3(-1.905,-2.972) 4(-0.635,-2.972) 5(0.635,-2.972) 6(1.905,-2.972) 7(3.175,-2.972) 8(4.445,-2.972) 9(4.445,2.972) 10(3.175,2.972) 11(1.905,2.972) 12(0.635,2.972) 13(-0.635,2.972) 14(-1.905,2.972) 15(-3.175,2.972) 16(-4.445,2.972)
  silkscreen extent -4.98,-1.85 4.98,1.83
SOT-23-3_L2.9-W1.6-P1.90-LS2.8-BR [mm]
  round 0 smd: 1(1.25,-0.95) 2(1.25,0.95) 3(-1.25,0)
  Top Layer region: -0.625,0.35 -0.625,-0.35 -1.875,-0.35 -1.875,0.35
  Top Layer region: 1.875,1.3 1.875,0.6 0.625,0.6 0.625,1.3
  Top Layer region: 1.875,-0.6 1.875,-1.3 0.625,-1.3 0.625,-0.6
  silkscreen extent -0.65,-1.46 0.9,1.46
SOT-23-6_L2.9-W1.6-P0.95-LS2.8-BL [mm]
  rect 0.55x1 smd: 1(-0.95,-1.4) 2(0,-1.4) 3(0.95,-1.4) 4(0.95,1.4) 5(0,1.4) 6(-0.95,1.4)
  silkscreen extent -1.78,-1.52 1.55,0.9
SOT-23_L2.9-W1.3-P0.95-LS2.4-BR#1 [mm]
  round 0 smd: 1(1.2,-0.95) 2(1.2,0.95) 3(-1.2,0)
  Top Layer region: 1.85,0.65 0.55,0.65 0.55,1.25 1.85,1.25
  Top Layer region: -0.55,-0.3 -1.85,-0.3 -1.85,0.3 -0.55,0.3
  Top Layer region: 1.85,-1.25 0.55,-1.25 0.55,-0.65 1.85,-0.65
  silkscreen extent -0.7,-1.5 0.7,1.5
SOT-23_L2.9-W1.3-P0.95-LS2.4-BR#2 [mm]
  rect 1.3x0.6 smd: 1(1.2,-0.95) 2(1.2,0.95) 3(-1.2,0)
  silkscreen extent -0.7,-1.5 0.7,1.5
SOT-89_L4.5-W2.5-P1.50-LS4.2-BR [mm]
  oval 1.9x0.7 smd: 1(1.25,-1.5) 3(1.25,1.5)
  oval 3.5x2 smd: 2(-1.25,0)
  oval 2.1x0.7 smd: 2(1.151,0)
  silkscreen extent -1.85,-2.3 0.75,2.3
SOT-323-3_L2.2-W1.3-P1.30-LS2.2-BR#1 [mil]
  round 0 smd: 1(40,-26) 2(40,26) 3(-40,0)
  Top Layer region: 19.25,-42.25 19.25,-9.75 60.75,-9.75 60.75,-42.25
  Top Layer region: 19.25,9.75 19.25,42.25 60.75,42.25 60.75,9.75
  Top Layer region: -60.75,-16.25 -60.75,16.25 -19.25,16.25 -19.25,-16.25
  silkscreen extent -40,-37 4,37
SOT-323-3_L2.2-W1.3-P1.30-LS2.2-BR#2 [mil]
  rect 41.5x32.5 smd: 1(40,-26) 2(40,26) 3(-40,0)
  silkscreen extent -40,-37 4,37
SSOP-28_L9.9-W3.9-P0.64-LS6.0-BL [mil]
  oval 15.75x64.06 smd: 1(-162.5,-112) 2(-137.5,-112) 3(-112.5,-112) 4(-87.5,-112) 5(-62.5,-112) 6(-37.5,-112) 7(-12.5,-112) 8(12.5,-112) 9(37.5,-112) 10(62.5,-112) 11(87.5,-112) 12(112.5,-112) 13(137.5,-112) 14(162.5,-112) 15(162.5,112) 16(137.5,112) 17(112.5,112) 18(87.5,112) 19(62.5,112) 20(37.5,112) 21(12.5,112) 22(-12.5,112) 23(-37.5,112) 24(-62.5,112) 25(-87.5,112) 26(-112.5,112) 27(-137.5,112) 28(-162.5,112)
  silkscreen extent -195,-111 195,71
TO-263-7_L10.2-W10.4-P1.27-LS14.4-B [mil]
  round 0 smd: 1(210,-150) 2(210,-100) 3(210,-50) 4(210,0) 5(210,50) 6(210,100) 7(210,150) 8(-210,0)
  Top Layer region: -22.99,206.69 -22.99,-206.69 -397.01,-206.69 -397.01,206.69
  Top Layer region: 278.9,167.72 278.9,132.28 141.1,132.28 141.1,167.72
  Top Layer region: 278.9,117.72 278.9,82.28 141.1,82.28 141.1,117.72
  Top Layer region: 278.9,67.72 278.9,32.28 141.1,32.28 141.1,67.72
  Top Layer region: 278.9,17.72 278.9,-17.72 141.1,-17.72 141.1,17.72
  Top Layer region: 278.9,-32.28 278.9,-67.72 141.1,-67.72 141.1,-32.28
  Top Layer region: 278.9,-82.28 278.9,-117.72 141.1,-117.72 141.1,-82.28
  Top Layer region: 278.9,-132.28 278.9,-167.72 141.1,-167.72 141.1,-132.28
  silkscreen extent -10,-201 123,197
TQFP-32_L7.0-W7.0-P0.80-LS9.0-BL [mm]
  oval 0.45x1.65 smd: 1(-2.817,-4.369) 2(-2.017,-4.369) 3(-1.217,-4.369) 4(-0.417,-4.369) 5(0.381,-4.369) 6(1.181,-4.369) 7(1.981,-4.369) 8(2.781,-4.369) 17(2.791,4.369) 18(1.991,4.369) 19(1.191,4.369) 20(0.391,4.369) 21(-0.406,4.369) 22(-1.207,4.369) 23(-2.007,4.369) 24(-2.807,4.369)
  oval 1.65x0.45 smd: 9(4.381,-2.804) 10(4.381,-2.004) 11(4.381,-1.204) 12(4.381,-0.404) 13(4.381,0.394) 14(4.381,1.194) 15(4.381,1.994) 16(4.381,2.794) 25(-4.381,2.804) 26(-4.381,2.004) 27(-4.381,1.204) 28(-4.381,0.404) 29(-4.381,-0.394) 30(-4.381,-1.194) 31(-4.381,-1.994) 32(-4.381,-2.794)
  silkscreen extent -3.86,-4.45 2.94,2.95
TQFP-100_14X14X05P [mm]
  oval 1.646x0.28 smd: 1(-1.6,-1.6) 2(-1.6,-2.1) 3(-1.6,-2.6) 4(-1.6,-3.1) 5(-1.6,-3.6) 6(-1.6,-4.1) 7(-1.6,-4.6) 8(-1.6,-5.1) 9(-1.6,-5.6) 10(-1.6,-6.1) 11(-1.6,-6.6) 12(-1.6,-7.1) 13(-1.6,-7.6) 14(-1.6,-8.1) 15(-1.6,-8.6) 16(-1.6,-9.1) 17(-1.6,-9.6) 18(-1.6,-10.1) 19(-1.6,-10.6) 20(-1.6,-11.1) 21(-1.6,-11.6) 22(-1.6,-12.1) 23(-1.6,-12.6) 24(-1.6,-13.1) 25(-1.6,-13.6) 51(13.6,-13.6) 52(13.6,-13.1) 53(13.6,-12.6) 54(13.6,-12.1) 55(13.6,-11.6) 56(13.6,-11.1) 57(13.6,-10.6) 58(13.6,-10.1) 59(13.6,-9.6) 60(13.6,-9.1) 61(13.6,-8.6) 62(13.6,-8.1) 63(13.6,-7.6) 64(13.6,-7.1) 65(13.6,-6.6) 66(13.6,-6.1) 67(13.6,-5.6) 68(13.6,-5.1) 69(13.6,-4.6) 70(13.6,-4.1) 71(13.6,-3.6) 72(13.6,-3.1) 73(13.6,-2.6) 74(13.6,-2.1) 75(13.6,-1.6)
  oval 0.28x1.646 smd: 26(0,-15.2) 27(0.5,-15.2) 28(1,-15.2) 29(1.5,-15.2) 30(2,-15.2) 31(2.5,-15.2) 32(3,-15.2) 33(3.5,-15.2) 34(4,-15.2) 35(4.5,-15.2) 36(5,-15.2) 37(5.5,-15.2) 38(6,-15.2) 39(6.5,-15.2) 40(7,-15.2) 41(7.5,-15.2) 42(8,-15.2) 43(8.5,-15.2) 44(9,-15.2) 45(9.5,-15.2) 46(10,-15.2) 47(10.5,-15.2) 48(11,-15.2) 49(11.5,-15.2) 50(12,-15.2) 76(12,0) 77(11.5,0) 78(11,0) 79(10.5,0) 80(10,0) 81(9.5,0) 82(9,0) 83(8.5,0) 84(8,0) 85(7.5,0) 86(7,0) 87(6.5,0) 88(6,0) 89(5.5,0) 90(5,0) 91(4.5,0) 92(4,0) 93(3.5,0) 94(3,0) 95(2.5,0) 96(2,0) 97(1.5,0) 98(1,0) 99(0.5,0) 100(0,0)
  silkscreen extent -2.15,-13.98 12.37,-0.8
USB-A-TH_USB-M-51 [mm]
  round 1.7 hole 1.1: 1(-3.5,2.574) 2(-1.001,2.574) 3(1.001,2.574) 4(3.5,2.574) 5(-3.5,-0.027) 6(-1.001,-0.027) 7(1.001,-0.027) 8(3.5,-0.027)
  round 3.2 hole 2.3: 9(-6.551,-2.925) 9(-6.551,2.925) 9(6.551,-2.826) 9(6.551,2.925)
  silkscreen extent -7.52,-14.13 7.54,3.87
USB-C-SMD_KH-TYPE-C-16P#1 [mm]
  oval 1.2x2 hole 0.7 slot 1.7 at 90 deg copper offset 0,0: 1(-4.32,1.765) 2(4.32,1.765)
  oval 1.2x1.8 hole 0.7 slot 1.4 at 90 deg copper offset 0,0: 3(-4.32,-2.415)
  oval 1.2x1.8 hole 0.7 slot 1.4 at 90 deg: 4(4.32,-2.415)
  round 0 smd: A1(-3.35,2.415) A4(-2.55,2.415) A5(-1.25,2.415) A6(-0.25,2.415) A7(0.25,2.415) A8(1.25,2.415) A9(2.55,2.415) A12(3.35,2.415) B1(3.05,2.415) B4(2.25,2.415) B5(1.75,2.415) B6(0.75,2.415) B7(-0.75,2.415) B8(-1.75,2.415) B9(-2.25,2.415) B12(-3.05,2.415)
  round 0.7 hole 0.7 unplated: ""(-2.89,1.235) ""(2.89,1.235)
  Top Layer region: -3.5,3.065 -3.2,3.065 -3.2,1.765 -3.5,1.765
  Top Layer region: -3.2,3.065 -2.9,3.065 -2.9,1.765 -3.2,1.765
  Top Layer region: -2.7,3.065 -2.4,3.065 -2.4,1.765 -2.7,1.765
  Top Layer region: -2.4,3.065 -2.1,3.065 -2.1,1.765 -2.4,1.765
  Top Layer region: -1.9,3.065 -1.6,3.065 -1.6,1.765 -1.9,1.765
  Top Layer region: -1.4,3.065 -1.1,3.065 -1.1,1.765 -1.4,1.765
  Top Layer region: -0.9,3.065 -0.6,3.065 -0.6,1.765 -0.9,1.765
  Top Layer region: -0.4,3.065 -0.1,3.065 -0.1,1.765 -0.4,1.765
  Top Layer region: 0.1,3.065 0.4,3.065 0.4,1.765 0.1,1.765
  Top Layer region: 0.6,3.065 0.9,3.065 0.9,1.765 0.6,1.765
  Top Layer region: 1.1,3.065 1.4,3.065 1.4,1.765 1.1,1.765
  Top Layer region: 1.6,3.065 1.9,3.065 1.9,1.765 1.6,1.765
  Top Layer region: 2.1,3.065 2.4,3.065 2.4,1.765 2.1,1.765
  Top Layer region: 2.4,3.065 2.7,3.065 2.7,1.765 2.4,1.765
  Top Layer region: 2.9,3.065 3.2,3.065 3.2,1.765 2.9,1.765
  Top Layer region: 3.2,3.065 3.5,3.065 3.5,1.765 3.2,1.765
  silkscreen extent -4.57,-5.08 4.57,0.57
USB-C-SMD_KH-TYPE-C-16P#2 [mm]
  oval 1.2x2 hole 0.7 slot 1.7 at 90 deg copper offset 0,0: 1(-4.32,1.765) 2(4.32,1.765)
  oval 1.2x1.8 hole 0.7 slot 1.4 at 90 deg: 3(-4.32,-2.415)
  oval 1.2x1.8 hole 0.7 slot 1.4 at 90 deg copper offset 0,0: 4(4.32,-2.415)
  round 0 smd: A1(-3.35,2.415) A4(-2.55,2.415) A5(-1.25,2.415) A6(-0.25,2.415) A7(0.25,2.415) A8(1.25,2.415) A9(2.55,2.415) A12(3.35,2.415) B1(3.05,2.415) B4(2.25,2.415) B5(1.75,2.415) B6(0.75,2.415) B7(-0.75,2.415) B8(-1.75,2.415) B9(-2.25,2.415) B12(-3.05,2.415)
  round 0.7 hole 0.7 unplated: ""(-2.89,1.235) ""(2.89,1.235)
  Top Layer region: -3.5,3.065 -3.2,3.065 -3.2,1.765 -3.5,1.765
  Top Layer region: -3.2,3.065 -2.9,3.065 -2.9,1.765 -3.2,1.765
  Top Layer region: -2.7,3.065 -2.4,3.065 -2.4,1.765 -2.7,1.765
  Top Layer region: -2.4,3.065 -2.1,3.065 -2.1,1.765 -2.4,1.765
  Top Layer region: -1.9,3.065 -1.6,3.065 -1.6,1.765 -1.9,1.765
  Top Layer region: -1.4,3.065 -1.1,3.065 -1.1,1.765 -1.4,1.765
  Top Layer region: -0.9,3.065 -0.6,3.065 -0.6,1.765 -0.9,1.765
  Top Layer region: -0.4,3.065 -0.1,3.065 -0.1,1.765 -0.4,1.765
  Top Layer region: 0.1,3.065 0.4,3.065 0.4,1.765 0.1,1.765
  Top Layer region: 0.6,3.065 0.9,3.065 0.9,1.765 0.6,1.765
  Top Layer region: 1.1,3.065 1.4,3.065 1.4,1.765 1.1,1.765
  Top Layer region: 1.6,3.065 1.9,3.065 1.9,1.765 1.6,1.765
  Top Layer region: 2.1,3.065 2.4,3.065 2.4,1.765 2.1,1.765
  Top Layer region: 2.4,3.065 2.7,3.065 2.7,1.765 2.4,1.765
  Top Layer region: 2.9,3.065 3.2,3.065 3.2,1.765 2.9,1.765
  Top Layer region: 3.2,3.065 3.5,3.065 3.5,1.765 3.2,1.765
  silkscreen extent -4.57,-5.08 4.57,0.57
"WEMOS-D1 ESP32" [mil]
  round 72 hole 40: 1(0,-100) 2(100,-100) 3(1000,-100) 4(1100,-100) 5(0,-200) 6(100,-200) 7(1000,-200) 8(1100,-200) 9(0,-300) 10(100,-300) 11(1000,-300) 12(1100,-300) 13(0,-400) 14(100,-400) 15(1000,-400) 16(1100,-400) 17(0,-500) 18(100,-500) 19(1000,-500) 20(1100,-500) 21(0,-600) 22(100,-600) 23(1000,-600) 24(1100,-600) 25(0,-700) 26(100,-700) 27(1000,-700) 28(1100,-700) 29(0,-800) 30(100,-800) 31(1000,-800) 32(1100,-800) 33(0,-900) 34(100,-900) 35(1000,-900) 36(1100,-900) 37(0,-1000) 38(1000,-1000) 39(100,-1000) 40(1100,-1000)
  silkscreen extent -102,-1384 1202,200

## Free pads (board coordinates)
  round 0 hole 2 slot 28 at 90 deg unplated: 1(103.787,39.1)
  round 0 hole 2 slot 44 at 90 deg unplated: 1(190.887,78.4) 1(190.887,123.4)
  round 0 hole 2 slot 8 at 0 deg unplated: 1(197.487,104.2)

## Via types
v1: diameter 0.6, hole 0.3, Top Layer to Bottom Layer, 381 vias
v2: diameter 0.61, hole 0.305, Top Layer to Bottom Layer, 1 vias

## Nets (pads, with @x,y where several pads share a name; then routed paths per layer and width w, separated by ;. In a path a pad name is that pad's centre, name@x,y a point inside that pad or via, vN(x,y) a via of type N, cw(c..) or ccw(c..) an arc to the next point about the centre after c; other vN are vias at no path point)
1V8HUB: C12.2 U2.12 U2.28 | length 14.8
  Top Layer w0.3: U2.28@95.442,67.273 96.115,67.273 96.988,66.4 96.988,65.501 97.288,65.201 C12.2@97.287,65 97.587,65.3 97.587,68 99.287,69.7 v1(99.287,70.9) ; v1(99.787,73.8) 100.245,74.258 U2.12@101.132,74.258
  Bottom Layer w0.3: v1(99.287,70.9) 99.287,73.3 v1(99.787,73.8)
3V3HUB: C10.2 Q7.3 R2.2 R34.2 U2.13 U2.19 U2.21 U2.26 | length 37.5
  Top Layer w0.145: 90.686,75.099 90.686,74.8 90.087,74.8 89.736,74.449 89.736,73.451 89.889,73.301 Q7.3@92.553,73.301
  Top Layer w0.15: R2.2@90.687,66.4 91.486,67.2 92.637,67.2 93.98,68.544 U2.26@95.444,68.544
  Top Layer w0.3: Q7.3@92.553,73.3 92.916,72.938 96.486,72.938 ; U2.21@95.443,71.668 96.987,71.6 97.287,71.946 97.287,72.555 96.9,72.938 U2.19@95.443,72.938 ; U2.19@95.444,72.989 96.874,72.989 97.186,73.299 v1@97.186,75.099 ; 96.587,69 96.13,68.543 U2.26@95.442,68.543 96.132,68.544 96.388,68.8 96.587,69.001 96.587,71.5 ; U2.13@101.132,74.893 100.195,74.893 v1(99.887,75.2) 99.887,75.7 100.287,76.1 102.586,76.1 103.587,77.101 C10.2@103.587,77.3
  Bottom Layer w0.3: v1(97.187,75.1) 97.287,75.2 v1(99.887,75.2)
5V_1: 5V.1 R70.2 | length 1.3
  Top Layer w0.145: 5V.1@99.737,104.6 R70.2@101.087,104.6
+3V3: C15.1 C36.1 C41.2 C42.2 C43.2 C45.2 C46.2 C47.2 C48.2 C49.2 C50.2 C51.2 C52.1 C54.2 CN6.1 CN15.1 J13.1 Q3.1 Q4.1 Q5.1 R29.2 R30.2 R37.2 R78.1 R79.1 RX485.2 RXCAN1.2 RXCAN.2 TX485.2 TXCAN1.2 TXCAN.2 U1.30 U7.5 U8.8 U11.1 U11.10 U11.11 U11.21 U11.31 U11.32 U11.33 U11.45 U11.50 U11.54 U11.75 U11.76 U11.99 U12.5 U13.1 U18.1 U18.14 | length 298.8
  Top Layer w0.145: R79.1@81.486,83.301 80.686,83.301 80.386,83.001 80.386,81.2 84.186,77.401 84.186,77.101 85.286,76.001 89.289,76.001 90.313,77.025 CN6.1@91.437,77.025 92.512,77.025 93.287,77.799 93.287,81.5 v1(93.387,81.5) ; R79.1@81.487,83.3 R78.1@82.987,83.3 ; C51.2@101.987,87.1 U11.21@103.787,87.1 104.986,87.101 107.887,84.2 U11.31@107.887,83.5 ; C47.2@102.087,97.1 U11.1@103.787,97.1 104.987,97.1 105.887,98 U11.99@105.887,98.7 C46.2@105.887,100.5 ; U11.11@103.787,92.1 102.087,92.1 102.587,92.6 U11.10@103.787,92.6 ; U11.31@107.887,83.5 107.887,82.7 C54.2@108.887,81.7 ; v1(108.387,84.8) U11.32@108.387,83.5 108.387,82.2 C54.2@108.887,81.7 ; U11.33@108.887,83.5 C54.2@108.888,81.701 ; C50.2@114.987,81.7 114.887,81.8 U11.45@114.887,83.5 114.887,84.2 117.287,86.6 U11.54@118.987,86.6 120.987,86.6 v1(120.287,87.3) ; 116.289,85.602 116.387,85.5 117.387,84.5 U11.50@117.387,83.5 117.387,82.3 ; C43.2@117.287,100.4 117.387,100.3 U11.76@117.387,98.7 117.387,98 118.287,97.1 U11.75@118.987,97.1 ; U11.75@118.987,97.101 125.537,97.1 ; 125.223,97.101 125.588,97.101 125.887,97.4 126.938,97.4 128.138,96.199 RXCAN1.2@128.137,94.8 ; U12.5@125.52,88.61 126.697,88.609 C45.2@126.787,88.7 ; C45.2@126.787,88.7 126.987,88.9 v1(126.987,89.6) ; CN15.1@127.087,70.33 127.087,70.301 130.44,70.301 ; CN15.1@127.087,70.33 128.417,70.33 C15.1@129.087,71 129.786,70.301 U18.1@130.439,70.301 ; TXCAN1.2@128.137,93.3 RXCAN1.2@128.137,94.8 ; U18.14@130.089,72.151 130.587,72.15 130.587,70.301 130.44,70.301 ; 130.587,71.593 130.595,71.6 v1(131.687,71.6) ; R29.2@135.539,70.851 135.539,72.351 ; Q5.1@140.571,83.36 140.727,83.359 141.387,82.699 141.387,81 140.747,80.36 Q4.1@140.571,80.36 138.347,80.36 138.187,80.2 138.187,79.199 138.387,79.001 139.087,79 J13.1@141.057,77 ; Q5.1@140.571,83.36 140.748,83.361 141.387,84 141.387,85.545 Q3.1@140.571,86.36 ; U7.5@162.278,117.333 163.455,117.332 166.635,114.152 173.688,114.152 RXCAN.2@174.437,113.4 TXCAN.2@174.437,111.9 ; RX485.2@176.037,89.9 TX485.2@176.037,91.4
  Top Layer w0.2: U8.8@145.182,103.12 145.182,102.405 145.887,101.7 146.487,101.7 149.687,98.5 149.687,96.2 v1(153.187,92.7) 156.187,92.7 157.587,91.3 159.586,91.3 160.786,90.1 172.087,90.1 173.287,91.3 173.287,92.201 173.686,92.6 174.989,92.6 176.038,91.551 TX485.2@176.038,91.401
  Top Layer w0.3: v1(124.387,80.5) 125.987,80.5 127.287,80.5 127.887,79.9 130.287,79.9 130.887,80.5 131.487,81.1 131.687,81.1 132.587,81.1 133.087,81.6 133.687,82.2 139.087,82.2 139.287,82.4 139.287,82.9 139.287,85.2 140.394,86.307 140.625,86.307 141.518,87.2 145.487,87.2 146.887,87.2 v1(147.587,87.9) ; 145.182,103.121 145.187,105.699 148.088,108.599 171.138,108.599 TXCAN.2@174.437,111.9
  Top Layer w0.5: 116.887,85.6 v1(118.987,83.5) ; v1(124.387,76.9) 124.387,75.2 124.587,75
  Top Layer w0.8: C52.1@124.587,75.5 124.587,72.83 CN15.1@127.087,70.33
  Bottom Layer w0.145: v1(93.387,81.5) 93.387,83.099 93.688,83.4 93.793,83.499 103.066,83.499 103.368,83.199 ; 103.386,83.199 106.487,83.199 107.987,84.7 v1(108.387,84.8) ; v1(120.287,87.3) 121.087,87.299 121.788,86.601 123.988,86.601 v1(126.987,89.6) ; v1(131.687,71.6) v1(135.487,71.6)
  Bottom Layer w0.3: v1@147.587,87.901 147.986,87.901 152.787,92.699 v1(153.187,92.7) ; v1@161.588,90.301 161.588,88.599 160.587,87.601 160.587,85.8 161.247,85.14 162.748,85.14 164.029,83.86 U1.30@164.366,83.86
  Bottom Layer w0.5: v1(124.387,76.9) v1(124.387,80.5)
  Bottom Layer w0.6: v1(118.987,83.5) 121.387,83.5 v1(124.387,80.5)
  other v1: 161.587,90.3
